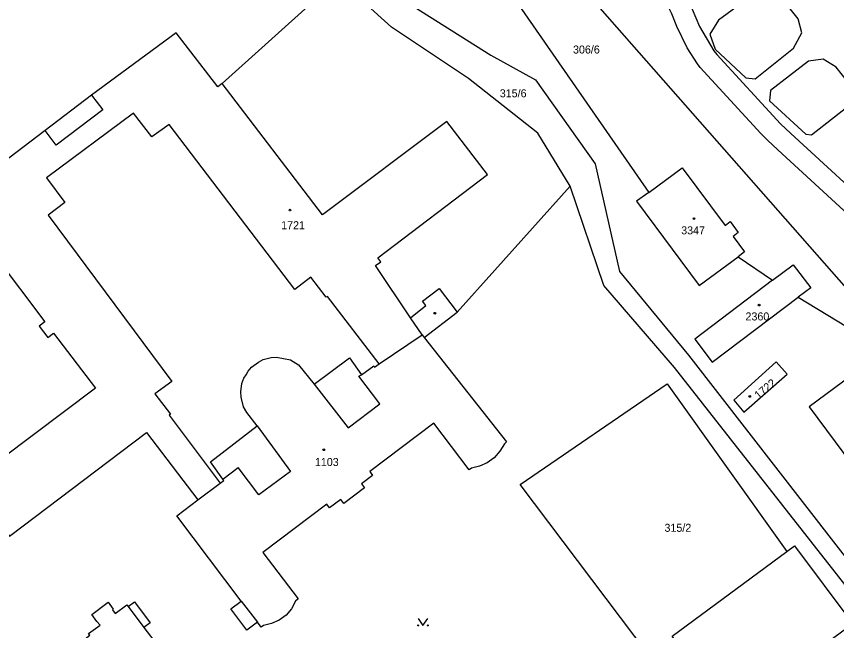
# Model space of a CAD drawing. Extents: x -679220 to -673243, y -1075091 to -1066557.
# Drawn here: x -676420.8 to -676246.6, y -1072555.7 to -1072425.2 of the extents above; entities that cross this region are included whole.
import ezdxf

# ---------------------------------------------------------------- set-up
doc = ezdxf.new("R2010")
doc.units = 0
for name, color, linetype in [('Hranice parcel', 7, 'Continuous'), ('Parcelní čísla', 7, 'Continuous'), ('Vnitřní kresba', 7, 'Continuous'), ('Značky budov', 7, 'Continuous'), ('Značky kultur', 7, 'Continuous')]:
    doc.layers.add(name, color=color, linetype=linetype)

msp = doc.modelspace()

# ---------------------------------------------------------------- linework, layer by layer
at = {"layer": 'Hranice parcel'}
for p, q in [((-676336.42, -1072390.58), (-676286.47, -1072462.64)), ((-676267.51, -1072476.31), (-676260.16, -1072481.32))]:
    msp.add_line(p, q, dxfattribs=at)
for points in [[(-676240.63, -1072470.5), (-676259.07, -1072453.6), (-676261.24, -1072451.54), (-676262.68, -1072450.14), (-676275.53, -1072436.12), (-676276.14, -1072435.29), (-676278.28, -1072431.93), (-676280.47, -1072427.4), (-676281.58, -1072424.69), (-676282.94, -1072421.98), (-676284.05, -1072420.33), (-676305.09, -1072393.55), (-676309.65, -1072388.37), (-676315.86, -1072383.3), (-676328.19, -1072374.47), (-676335.83, -1072368.19), (-676340.22, -1072364.01), (-676372.73, -1072328.75), (-676374.02, -1072328.04)], [(-676227.86, -1072501.86), (-676299.88, -1072419.89), (-676371.63, -1072338.06)], [(-676393.87, -1072354.27), (-676392.79, -1072356.37), (-676350.62, -1072411.11), (-676336.27, -1072423.2), (-676320.05, -1072433.48), (-676310.5, -1072438.74), (-676297.87, -1072456.58), (-676292.66, -1072479.44), (-676278.01, -1072497.19), (-676240.58, -1072545.43), (-676237.18, -1072549.2), (-676240.15, -1072551.88)], [(-676292.07, -1072402.99), (-676279.41, -1072419.22), (-676277.22, -1072423.73), (-676275.71, -1072427.4), (-676272.62, -1072432.59), (-676272.04, -1072433.35), (-676258.47, -1072448.08), (-676256.31, -1072450.13), (-676236.39, -1072468.37), (-676234.99, -1072469.86), (-676232.52, -1072472.99), (-676208.52, -1072507.9)], [(-676356.54, -1072413.49), (-676355.6, -1072414.73), (-676355.09, -1072415.72), (-676354.88, -1072417.25), (-676355.09, -1072418.8), (-676355.57, -1072420.11), (-676357.38, -1072421.82), (-676377.07, -1072439.5), (-676378.04, -1072440.21), (-676386.9, -1072428.71), (-676404.85, -1072441.99), (-676414.73, -1072449.5), (-676433.17, -1072463.49), (-676424.44, -1072475.29), (-676425.42, -1072476.09), (-676414.74, -1072490.14), (-676415.99, -1072491.09), (-676414.16, -1072493.47), (-676412.92, -1072492.53), (-676404.02, -1072504.23), (-676430.73, -1072524.26), (-676422.26, -1072535.65), (-676393.2, -1072513.64), (-676382.24, -1072527.95)], [(-676303.18, -1072461.34), (-676310.03, -1072450.02), (-676324.78, -1072438.42), (-676341.09, -1072427.55), (-676356.54, -1072413.49)], [(-676286.47, -1072462.64), (-676279.35, -1072457.42), (-676270.27, -1072469.65), (-676269.19, -1072468.85), (-676267.46, -1072471.18), (-676268.54, -1072471.98), (-676266.1, -1072475.27), (-676267.51, -1072476.31)], [(-676334.15, -1072493.48), (-676327.17, -1072488.1), (-676303.18, -1072461.34)], [(-676240.15, -1072551.88), (-676280.98, -1072499.86), (-676296, -1072482.45), (-676303.18, -1072461.34)], [(-676286.47, -1072462.64), (-676289.05, -1072464.53), (-676275.77, -1072482.44), (-676267.51, -1072476.31)], [(-676260.16, -1072481.32), (-676255.79, -1072478.03), (-676252.07, -1072482.88), (-676254.72, -1072484.88)], [(-676260.16, -1072481.32), (-676276.71, -1072493.79), (-676272.98, -1072498.72), (-676254.72, -1072484.88)], [(-676254.72, -1072484.88), (-676238.18, -1072494.99), (-676227.86, -1072501.86)], [(-676334.15, -1072493.48), (-676316.66, -1072515.64), (-676317.14, -1072516.03), (-676318.1, -1072517.65), (-676319.31, -1072519.03), (-676320.82, -1072520.08), (-676322.43, -1072520.8), (-676324.11, -1072521.22), (-676324.59, -1072521.58), (-676332.14, -1072511.7), (-676345.73, -1072521.96), (-676345.13, -1072522.76), (-676347.52, -1072524.57), (-676346.88, -1072525.41), (-676351.26, -1072528.71), (-676351.89, -1072527.87), (-676354.29, -1072529.68), (-676354.89, -1072528.88), (-676368.48, -1072539.14), (-676360.95, -1072549.02), (-676361.49, -1072549.46), (-676362.34, -1072551.14), (-676363.53, -1072552.49), (-676364.96, -1072553.53), (-676366.63, -1072554.27), (-676368.34, -1072554.68), (-676368.84, -1072555.01), (-676369.61, -1072553.99), (-676371.83, -1072555.66), (-676375.25, -1072551.14), (-676373.03, -1072549.46), (-676386.72, -1072531.35), (-676382.24, -1072527.95)], [(-676382.24, -1072527.95), (-676377.51, -1072524.42), (-676376.74, -1072523.84), (-676376.94, -1072523.57), (-676379.58, -1072519.9), (-676369.63, -1072512.26), (-676371.82, -1072509.43), (-676372.53, -1072508.19), (-676373.03, -1072506.17), (-676373.14, -1072505.03), (-676372.89, -1072503.22), (-676372.49, -1072502.12), (-676372.03, -1072501.39), (-676371.59, -1072500.59), (-676370.85, -1072499.75), (-676369.39, -1072498.68), (-676368.41, -1072498.17), (-676366.68, -1072497.69), (-676365.53, -1072497.65), (-676362.61, -1072498.24), (-676360.85, -1072499.3), (-676357.55, -1072503.38), (-676350.04, -1072497.76), (-676347.51, -1072501.41), (-676344.9, -1072499.52), (-676344.72, -1072499.76), (-676343.77, -1072499.07), (-676334.61, -1072492.91), (-676334.15, -1072493.48)], [(-676266.26, -1072509.32), (-676257.09, -1072501.29), (-676259.39, -1072498.67), (-676268.43, -1072506.81), (-676266.26, -1072509.32)], [(-676225.34, -1072518.59), (-676239.89, -1072498.95), (-676252.37, -1072508.19), (-676237.91, -1072527.72), (-676225.34, -1072518.59)], [(-676269.31, -1072573.26), (-676274.23, -1072577.22), (-676313.76, -1072524.7), (-676282.57, -1072503.32), (-676257.12, -1072538.94)], [(-676257.12, -1072538.94), (-676255.51, -1072537.76), (-676243.1, -1072554.3), (-676269.14, -1072573.49), (-676269.31, -1072573.26)], [(-676269.31, -1072573.26), (-676281.53, -1072556.9), (-676257.12, -1072538.94)], [(-676401.33, -1072549.72), (-676400.22, -1072551.19), (-676400.38, -1072551.3), (-676399.8, -1072552.11), (-676397.37, -1072550.29), (-676397.09, -1072550.65), (-676395.73, -1072549.63), (-676392.37, -1072554.1), (-676393.73, -1072555.12), (-676390.71, -1072559.05), (-676398.86, -1072565.18), (-676401.78, -1072561.21), (-676403.16, -1072562.22), (-676404.01, -1072561.11), (-676405.19, -1072562.02), (-676406.94, -1072559.69), (-676405.77, -1072558.79), (-676406.54, -1072557.78), (-676405.19, -1072556.75), (-676405.47, -1072556.39), (-676403.03, -1072554.56), (-676403.71, -1072553.81), (-676404.81, -1072552.34), (-676401.33, -1072549.72)]]:
    msp.add_lwpolyline(points, dxfattribs=at)
at = {"layer": 'Vnitřní kresba'}
for p, q in [((-676261.34, -1072418.44), (-676271.66, -1072426.06)), ((-676254.74, -1072425.78), (-676260.31, -1072418.66)), ((-676271.66, -1072426.06), (-676273.5, -1072429.05)), ((-676253.95, -1072428.75), (-676254.74, -1072425.78)), ((-676273.5, -1072429.05), (-676272.39, -1072432.2)), ((-676255.72, -1072431.97), (-676253.95, -1072428.75)), ((-676272.39, -1072432.2), (-676265.84, -1072438.27)), ((-676263.86, -1072438.49), (-676255.72, -1072431.97)), ((-676252.5, -1072434.78), (-676260.63, -1072440.99)), ((-676249.41, -1072434.31), (-676252.5, -1072434.78)), ((-676246.69, -1072436.04), (-676249.41, -1072434.31)), ((-676242.61, -1072441.15), (-676246.69, -1072436.04)), ((-676265.84, -1072438.27), (-676263.86, -1072438.49)), ((-676355.81, -1072467.37), (-676377.07, -1072439.5)), ((-676260.63, -1072440.99), (-676260.8, -1072443.19)), ((-676404.85, -1072441.99), (-676402.46, -1072445.09)), ((-676260.8, -1072443.19), (-676253.07, -1072450.26)), ((-676251.91, -1072450.4), (-676242.78, -1072443.25)), ((-676402.46, -1072445.09), (-676412.37, -1072452.57)), ((-676395.92, -1072445.81), (-676414.43, -1072459.54)), ((-676392.02, -1072450.86), (-676395.92, -1072445.81)), ((-676388.33, -1072448.24), (-676392.02, -1072450.86)), ((-676361.68, -1072483.25), (-676388.33, -1072448.24)), ((-676329.35, -1072447.56), (-676355.81, -1072467.37)), ((-676320.7, -1072458.83), (-676329.35, -1072447.56)), ((-676412.37, -1072452.57), (-676414.73, -1072449.5)), ((-676253.07, -1072450.26), (-676251.91, -1072450.4)), ((-676344.03, -1072476.52), (-676320.7, -1072458.83)), ((-676414.43, -1072459.54), (-676410.49, -1072464.75)), ((-676410.49, -1072464.75), (-676414.09, -1072467.49)), ((-676414.09, -1072467.49), (-676387.8, -1072502.83)), ((-676343.36, -1072477.37), (-676344.03, -1072476.52)), ((-676344.51, -1072478.14), (-676343.36, -1072477.37)), ((-676337.06, -1072489.26), (-676344.51, -1072478.14)), ((-676358.23, -1072480.65), (-676361.68, -1072483.25)), ((-676354.99, -1072484.88), (-676358.23, -1072480.65)), ((-676334.54, -1072485.75), (-676331.01, -1072483.06)), ((-676331.01, -1072483.06), (-676327.17, -1072488.1)), ((-676354.72, -1072484.73), (-676354.99, -1072484.88)), ((-676343.77, -1072499.07), (-676354.72, -1072484.73)), ((-676337.06, -1072489.26), (-676333.85, -1072486.65)), ((-676333.85, -1072486.65), (-676334.54, -1072485.75)), ((-676334.61, -1072492.91), (-676337.06, -1072489.26)), ((-676387.8, -1072502.83), (-676391.37, -1072505.46)), ((-676348.06, -1072501.7), (-676347.51, -1072501.41)), ((-676343.62, -1072507.57), (-676348.06, -1072501.7)), ((-676357.55, -1072503.38), (-676350.33, -1072512.65)), ((-676391.37, -1072505.46), (-676388.08, -1072509.76)), ((-676350.33, -1072512.65), (-676343.62, -1072507.57)), ((-676388.08, -1072509.76), (-676388.33, -1072509.97)), ((-676388.33, -1072509.97), (-676377.51, -1072524.42)), ((-676369.63, -1072512.26), (-676362.58, -1072521.95)), ((-676376.94, -1072523.57), (-676373.7, -1072521.11)), ((-676369.3, -1072526.91), (-676373.7, -1072521.11)), ((-676362.58, -1072521.95), (-676369.3, -1072526.91)), ((-676373.03, -1072549.46), (-676369.61, -1072553.99)), ((-676397.09, -1072550.65), (-676393.73, -1072555.12))]:
    msp.add_line(p, q, dxfattribs=at)
at = {"layer": 'Značky budov'}
for centre in [(-676362.68, -1072466.4), (-676276.84, -1072468.19), (-676263.03, -1072486.59), (-676331.91, -1072488.31), (-676265, -1072505.99), (-676355.51, -1072517.32)]:
    msp.add_circle(centre, 0.175, dxfattribs=at)
at = {"layer": 'Značky kultur'}
msp.add_lwpolyline([(-676335.43, -1072553.15), (-676334.43, -1072554.65), (-676333.43, -1072553.15)], dxfattribs=at)
for centre in [(-676335.43, -1072554.65), (-676333.43, -1072554.65)]:
    msp.add_circle(centre, 0.1, dxfattribs=at)

# ---------------------------------------------------------------- texts
at = {"layer": 'Parcelní čísla'}
for s, p in [('306/6', (-676302.56, -1072433.13)), ('315/6', (-676318.12, -1072442.43)), ('1721', (-676364.56, -1072470.46)), ('3347', (-676279.58, -1072471.55)), ('2360', (-676265.92, -1072489.84)), ('1103', (-676357.4, -1072520.78)), ('315/2', (-676283.13, -1072534.75))]:
    msp.add_text(s, height=1.7, dxfattribs=at).set_placement(p)
msp.add_text('1722', height=1.7, rotation=40, dxfattribs=at).set_placement((-676263.15, -1072506.64))

doc.saveas('drawing.dxf')
